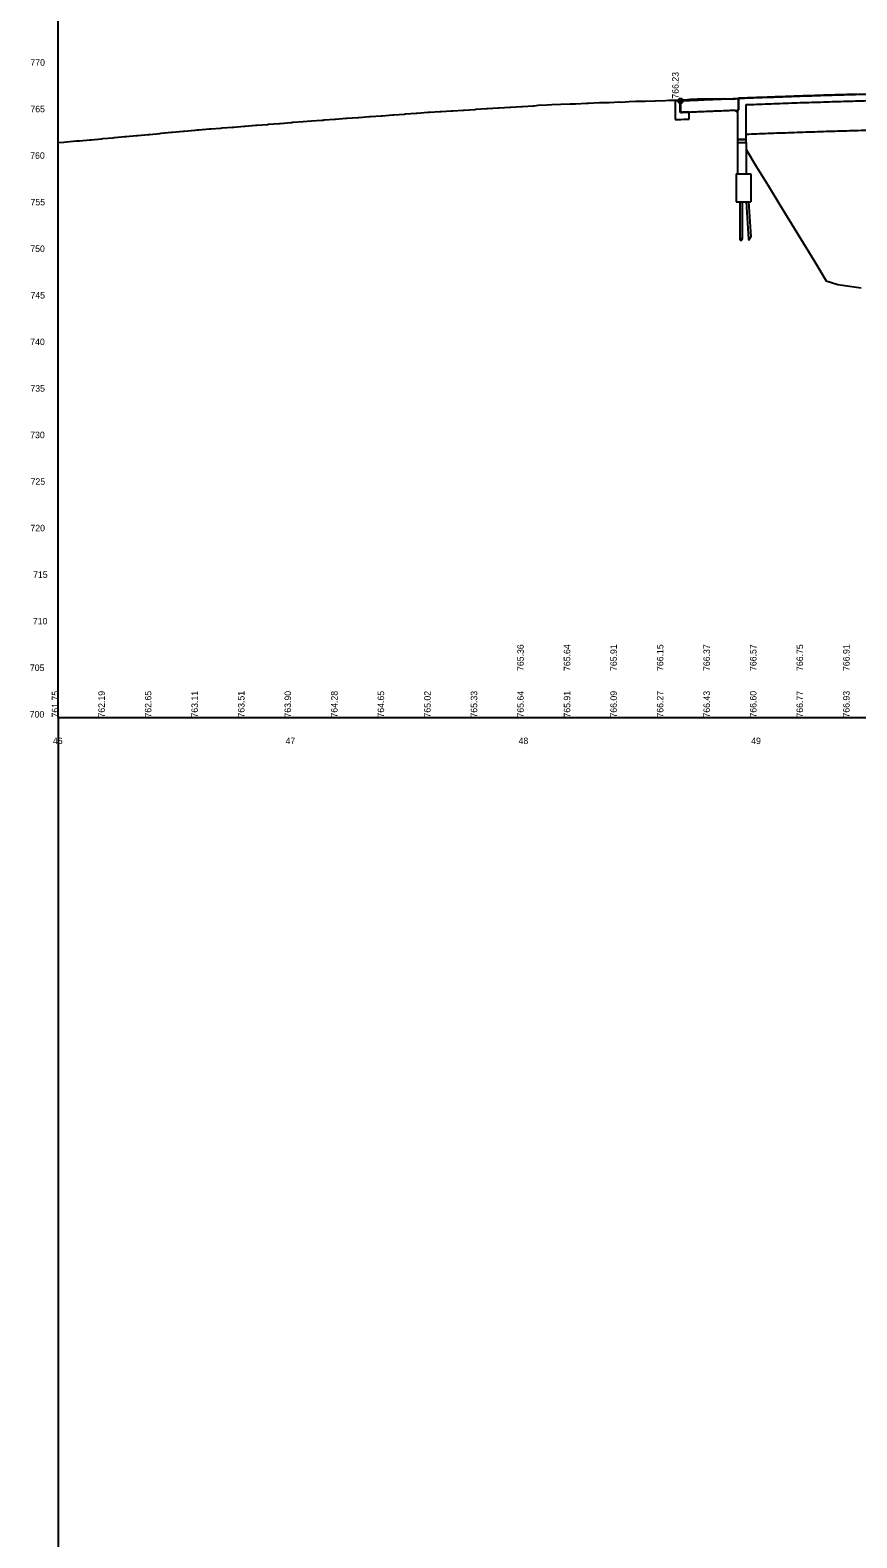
# Model space of a CAD drawing. Extents: x -209 to 3291, y 1080 to 3580.
# Drawn here: x -21 to 334, y 1728 to 2375 of the extents above; entities that cross this region are included whole.
import ezdxf

# ---------------------------------------------------------------- set-up
doc = ezdxf.new("R2010")
doc.units = 0
for name, color, linetype in [('BR_P_Gen_Approach_Slab', 7, 'Continuous'), ('BR_P_Gen_Approach_Slab_Hidden', 7, 'Continuous'), ('BR_P_Gen_Joint_Filler', 7, 'Continuous'), ('BR_P_Slab_Object', 7, 'Continuous'), ('BR_X_Sub_Foot_Object', 7, 'Continuous'), ('Default', 7, 'Continuous'), ('GK_Cells', 7, 'Continuous'), ('PF_P_Grade_Line', 7, 'Continuous'), ('PF_P_Sta_Elev_Text', 7, 'Continuous'), ('PF_P_Text', 7, 'Continuous'), ('PF_X_Ground_Line', 7, 'Continuous'), ('PF_X_Text', 7, 'Continuous')]:
    doc.layers.add(name, color=color, linetype=linetype)

msp = doc.modelspace()

# ---------------------------------------------------------------- linework, layer by layer
at = {"layer": 'BR_P_Gen_Approach_Slab'}
for p, q in [((256.35, 2345.06), (256.35, 2336.96)), ((258.57, 2345.06), (256.35, 2345.06)), ((258.35, 2345.06), (258.35, 2340.06)), ((262.36, 2337.23), (262.36, 2340.23))]:
    msp.add_line(p, q, dxfattribs=at)
msp.add_spline([(256.35, 2336.96), (261.27, 2337.18), (262.36, 2337.23)], degree=3, dxfattribs=at)
at = {"layer": 'BR_P_Gen_Approach_Slab_Hidden'}
for p, q in [((258.57, 2340.06), (258.57, 2345.06)), ((282.57, 2340.41), (282.24, 2341.06)), ((282.57, 2340.41), (283.07, 2340.43)), ((283.07, 2328.43), (286.83, 2328.43))]:
    msp.add_line(p, q, dxfattribs=at)
msp.add_spline([(258.57, 2340.06), (261.26, 2340.18), (271.26, 2340.61), (281.26, 2341.02), (282.24, 2341.06)], degree=3, dxfattribs=at)
at = {"layer": 'BR_P_Gen_Joint_Filler'}
for p, q in [((286.83, 2328.43), (283.07, 2328.43)), ((283.07, 2328.43), (283.07, 2327.1)), ((283.07, 2327.1), (286.83, 2327.1)), ((286.83, 2327.1), (286.83, 2328.43))]:
    msp.add_line(p, q, dxfattribs=at)
at = {"layer": 'BR_P_Slab_Object'}
for p, q in [((283.57, 2346.12), (283.57, 2341.12)), ((283.07, 2341.1), (283.57, 2341.12)), ((283.07, 2341.1), (283.07, 2327.1)), ((286.83, 2327.1), (286.83, 2343.41))]:
    msp.add_line(p, q, dxfattribs=at)
at = {"layer": 'BR_X_Sub_Foot_Object'}
for p, q in [((283.07, 2327.1), (283.07, 2313.73)), ((283.07, 2327.1), (286.83, 2327.1)), ((286.83, 2327.1), (286.83, 2313.73)), ((282.57, 2313.73), (282.57, 2301.73)), ((282.57, 2313.73), (288.84, 2313.73)), ((288.84, 2313.73), (288.84, 2301.73)), ((282.57, 2301.73), (288.84, 2301.73)), ((282.57, 2301.73), (284.57, 2301.73)), ((284.07, 2301.73), (284.07, 2285.6)), ((284.07, 2301.73), (285.07, 2301.73)), ((285.07, 2301.73), (285.07, 2285.6)), ((286.82, 2301.73), (287.83, 2285.6)), ((286.84, 2301.73), (287.84, 2301.73)), ((287.85, 2301.73), (288.8, 2286.57))]:
    msp.add_line(p, q, dxfattribs=at)
for centre, major_axis, start_param, end_param in [((288.12, 2285.01), (0, 1.32), 5.66656, 7.389768), ((288.5, 2287.16), (0, -1.32), 5.66656, 7.389768), ((284.32, 2284.75), (0, 1.32), 5.421581, 7.144789), ((284.32, 2286.46), (0, 1.32), 2.279989, 4.003197), ((284.82, 2286.46), (0, -1.32), 5.421581, 7.144789), ((288.02, 2286.68), (0, 1.32), 2.524967, 4.248175)]:
    msp.add_ellipse(centre, major_axis=major_axis, ratio=0.25, start_param=start_param, end_param=end_param, dxfattribs=at)
msp.add_spline([(286.83, 2330.74), (291.26, 2330.91), (301.26, 2331.28), (311.26, 2331.63), (321.26, 2331.96), (331.26, 2332.26), (341.26, 2332.55), (351.26, 2332.81), (361.26, 2333.06), (371.26, 2333.28), (381.26, 2333.48), (391.26, 2333.66), (401.26, 2333.82), (411.26, 2333.96), (421.26, 2334.07), (431.26, 2334.17), (441.26, 2334.24), (451.26, 2334.3), (461.26, 2334.33), (471.26, 2334.34), (481.26, 2334.33), (491.26, 2334.3), (501.26, 2334.25), (511.26, 2334.18), (521.26, 2334.09), (531.26, 2333.97), (541.26, 2333.84), (551.26, 2333.68), (561.26, 2333.51), (571.26, 2333.31), (581.26, 2333.09), (591.26, 2332.85), (596.07, 2332.73)], degree=3, dxfattribs=at)
at = {"layer": 'Default'}
for p, q in [((257.57, 2345.06), (256.35, 2345.06)), ((256.35, 2345.06), (256.35, 2336.96)), ((283.57, 2341.12), (283.57, 2345.98)), ((258.57, 2344.06), (258.57, 2340.06)), ((258.57, 2340.06), (258.57, 2344.06)), ((262.36, 2337.23), (262.36, 2340.23)), ((282.24, 2341.06), (282.57, 2340.41)), ((282.57, 2340.41), (283.07, 2340.43)), ((283.57, 2341.12), (283.07, 2341.1)), ((283.07, 2341.1), (283.28, 2341.11)), ((283.07, 2340.43), (283.07, 2341.1)), ((283.28, 2341.11), (283.57, 2341.12)), ((283.07, 2328.43), (286.83, 2328.43))]:
    msp.add_line(p, q, dxfattribs=at)
for points in [[(283.57, 2345.98), (280.55, 2345.81), (277.11, 2345.86)], [(283.57, 2346.12), (283.57, 2345.98), (283.57, 2341.12)], [(300.38, 2346.75), (300.37, 2346.75), (300.35, 2346.75)], [(283.07, 2341.1), (283.07, 2340.43), (283.07, 2328.43)], [(286.83, 2328.43), (286.83, 2330.74), (286.83, 2343.41)]]:
    msp.add_lwpolyline(points, dxfattribs=at)
for start, end in [(180, 270), (270, 2.55698)]:
    msp.add_arc((258.57, 2345.06), 1, start, end, dxfattribs=at)
for points in [[(277.11, 2345.86), (271.26, 2345.61), (261.26, 2345.18), (259.57, 2345.11)], [(300.35, 2346.75), (291.26, 2346.41), (283.57, 2346.12)], [(286.83, 2343.41), (291.26, 2343.58), (301.26, 2343.95), (311.26, 2344.3), (321.26, 2344.62), (331.26, 2344.93), (341.26, 2345.22), (351.26, 2345.48), (361.26, 2345.72), (371.26, 2345.94), (381.26, 2346.14), (391.26, 2346.32), (401.26, 2346.48), (411.26, 2346.62), (421.26, 2346.74), (431.26, 2346.83), (441.26, 2346.91), (451.26, 2346.96), (461.26, 2347), (471.26, 2347.01), (481.26, 2347), (491.26, 2346.97), (501.26, 2346.92), (511.26, 2346.85), (521.26, 2346.75), (531.26, 2346.64), (541.26, 2346.51), (551.26, 2346.35), (561.26, 2346.17), (571.26, 2345.97), (581.26, 2345.76), (591.26, 2345.52), (596.07, 2345.39)], [(334.38, 2347.85), (331.26, 2347.76), (321.26, 2347.46), (311.26, 2347.13), (301.26, 2346.78), (300.38, 2346.75)], [(256.35, 2336.96), (261.27, 2337.18), (262.36, 2337.23)]]:
    msp.add_spline(points, degree=3, dxfattribs=at)
for points in [[(258.57, 2340.06), (259.47, 2340.1), (260.36, 2340.14), (261.26, 2340.18), (264.59, 2340.33), (267.92, 2340.47), (271.26, 2340.61), (274.59, 2340.75), (277.92, 2340.89), (281.26, 2341.02), (281.59, 2341.04), (281.91, 2341.05), (282.24, 2341.06)], [(262.36, 2340.23), (261.99, 2340.21), (261.63, 2340.2), (261.26, 2340.18), (260.36, 2340.14), (259.47, 2340.1), (258.57, 2340.06)]]:
    msp.add_open_spline(points, degree=3, dxfattribs=at)
at = {"layer": 'GK_Cells'}
for q in [(-8.74, 3080.13), (3291.26, 2080.13), (-8.74, 1080.13)]:
    msp.add_line((-8.74, 2080.13), q, dxfattribs=at)
at = {"layer": 'PF_P_Grade_Line'}
for points in [[(258.57, 2345.06), (261.26, 2345.18), (271.26, 2345.61), (281.26, 2346.02), (291.26, 2346.41), (301.26, 2346.78), (311.26, 2347.13), (321.26, 2347.46), (331.26, 2347.76), (341.26, 2348.05), (351.26, 2348.31), (361.26, 2348.56), (371.26, 2348.78), (381.26, 2348.98), (391.26, 2349.16), (401.26, 2349.32), (411.26, 2349.46), (421.26, 2349.57), (431.26, 2349.67), (441.26, 2349.74), (451.26, 2349.8), (461.26, 2349.83), (471.26, 2349.84), (481.26, 2349.83), (491.26, 2349.8), (501.26, 2349.75), (511.26, 2349.68), (521.26, 2349.59), (531.26, 2349.47), (541.26, 2349.34), (551.26, 2349.18), (561.26, 2349.01), (571.26, 2348.81), (581.26, 2348.59), (591.26, 2348.35), (601.26, 2348.09), (611.26, 2347.81), (621.26, 2347.5), (624.33, 2347.41)], [(286.83, 2343.41), (291.26, 2343.58), (301.26, 2343.95), (311.26, 2344.3), (321.26, 2344.62), (331.26, 2344.93), (341.26, 2345.22), (351.26, 2345.48), (361.26, 2345.72), (371.26, 2345.94), (381.26, 2346.14), (391.26, 2346.32), (401.26, 2346.48), (411.26, 2346.62), (421.26, 2346.74), (431.26, 2346.83), (441.26, 2346.91), (451.26, 2346.96), (461.26, 2347), (471.26, 2347.01), (481.26, 2347), (491.26, 2346.97), (501.26, 2346.92), (511.26, 2346.85), (521.26, 2346.75), (531.26, 2346.64), (541.26, 2346.51), (551.26, 2346.35), (561.26, 2346.17), (571.26, 2345.97), (581.26, 2345.76), (591.26, 2345.52), (596.07, 2345.39)]]:
    msp.add_spline(points, degree=3, dxfattribs=at)
at = {"layer": 'PF_P_Text'}
msp.add_circle((258.57, 2345.06), 1, dxfattribs=at)
at = {"layer": 'PF_X_Ground_Line'}
for points in [[(-8.74, 2327.12), (-6.39, 2327.33), (-5.18, 2327.44), (-0.9, 2327.83), (-0.13, 2327.84), (0.43, 2327.89), (4.87, 2328.3), (5.43, 2328.35), (9.87, 2328.76), (10.42, 2328.81), (14.87, 2329.22), (15.41, 2329.27), (19.87, 2329.68), (20.41, 2329.73), (24.86, 2330.14), (25.4, 2330.19), (29.86, 2330.6), (30.39, 2330.65), (34.86, 2331.06), (35.39, 2331.11), (39.86, 2331.52), (40.38, 2331.57), (44.86, 2331.98), (45.38, 2332.03), (49.86, 2332.44), (50.01, 2332.46), (51.13, 2332.56), (51.64, 2332.61), (56.13, 2332.96), (56.63, 2333), (61.13, 2333.35), (61.62, 2333.39), (66.13, 2333.75), (66.61, 2333.79), (71.13, 2334.14), (71.6, 2334.18), (76.13, 2334.54), (76.59, 2334.58), (81.13, 2334.93), (81.58, 2334.97), (86.13, 2335.33), (86.57, 2335.36), (91.13, 2335.72), (91.56, 2335.76), (92.01, 2335.83), (96.48, 2336.18), (100.03, 2336.45), (104.53, 2336.79), (105, 2336.79), (105.42, 2336.82), (110, 2337.16), (110.42, 2337.19), (114.99, 2337.53), (115.43, 2337.56), (119.99, 2337.9), (120.43, 2337.93), (124.99, 2338.27), (125.44, 2338.3), (129.99, 2338.64), (130.44, 2338.67), (134.98, 2339.01), (135.45, 2339.04), (139.98, 2339.38), (140.45, 2339.41), (144.98, 2339.75), (145.46, 2339.78), (149.97, 2340.12), (150.15, 2340.14), (150.71, 2340.18), (155.23, 2340.46), (155.71, 2340.48), (160.23, 2340.77), (160.71, 2340.79), (165.24, 2341.08), (165.71, 2341.1), (170.25, 2341.39), (170.7, 2341.41), (175.26, 2341.69), (175.7, 2341.72), (180.26, 2342), (180.7, 2342.03), (185.27, 2342.31), (185.7, 2342.34), (190.28, 2342.62), (190.7, 2342.64), (195.29, 2342.93), (195.7, 2342.95), (197.46, 2343.13), (201.34, 2343.37), (203.3, 2343.5), (207.22, 2343.64), (211.17, 2343.78), (213.17, 2343.79), (213.55, 2343.81), (218.17, 2343.98), (219.06, 2344.07), (223.77, 2344.34), (224.57, 2344.37), (225.4, 2344.4), (227.98, 2344.39), (232.46, 2344.55)], [(232.46, 2344.55), (233.17, 2344.54), (236.6, 2344.74), (239.2, 2344.84), (241.84, 2344.93), (243.39, 2344.92), (247.76, 2345.08), (252.15, 2345.24), (253.43, 2345.32), (257.85, 2345.38), (259.15, 2345.42), (259.29, 2345.43), (260.35, 2345.51), (262.71, 2345.74), (263.66, 2345.78), (265.83, 2345.84), (276.61, 2345.86), (280.55, 2345.81), (283.9, 2346), (284.03, 2345.68)], [(285.37, 2346.4), (285.37, 2346.4), (285.37, 2346.4), (290.37, 2346.51), (295.37, 2346.64), (300.37, 2346.75), (305.37, 2347.01), (310.37, 2347.18), (315.37, 2347.37), (320.37, 2347.53), (325.37, 2347.69), (330.37, 2347.83), (335.37, 2347.86)], [(286.83, 2324.07), (291.26, 2316.74), (296.26, 2308.62), (301.26, 2300.43), (306.26, 2292.24), (311.26, 2284.06), (316.26, 2275.88), (321.26, 2267.71), (326.26, 2266.18), (331.26, 2265.46), (336.26, 2264.75)]]:
    msp.add_lwpolyline(points, dxfattribs=at)

# ---------------------------------------------------------------- texts
at = {"layer": 'GK_Cells'}
for s, p in [('450', (-8.74, 2081.6)), ('WINCHESTER', (-8.74, 2081.39)), ('4600.000000', (-8.74, 2081.18)), ('700', (-8.74, 2080.97)), ('20', (-8.74, 2080.76)), ('5', (-8.74, 2080.55)), ('NOGAP', (-8.74, 2080.34))]:
    msp.add_text(s, height=0.14, dxfattribs=at).set_placement(p)
at = {"layer": 'PF_P_Sta_Elev_Text'}
for s, p in [('770', (-20.73, 2360.13)), ('770', (-20.73, 2360.13)), ('765', (-20.73, 2340.13)), ('765', (-20.73, 2340.13)), ('760', (-20.82, 2320.13)), ('760', (-20.82, 2320.13)), ('755', (-20.69, 2300.13)), ('755', (-20.69, 2300.13)), ('750', (-20.77, 2280.13)), ('750', (-20.77, 2280.13)), ('745', (-20.71, 2260.13)), ('745', (-20.71, 2260.13)), ('740', (-20.8, 2240.13)), ('740', (-20.8, 2240.13)), ('735', (-20.73, 2220.13)), ('735', (-20.73, 2220.13)), ('730', (-20.82, 2200.13)), ('730', (-20.82, 2200.13)), ('725', (-20.64, 2180.13)), ('725', (-20.64, 2180.13)), ('720', (-20.73, 2160.13)), ('720', (-20.73, 2160.13)), ('715', (-19.58, 2140.13)), ('715', (-19.58, 2140.13)), ('710', (-19.67, 2120.13)), ('710', (-19.67, 2120.13)), ('705', (-20.95, 2100.13)), ('705', (-20.95, 2100.13)), ('700', (-21.04, 2080.13)), ('700', (-21.04, 2080.13)), ('46', (-11.05, 2068.73)), ('47', (88.9, 2068.73)), ('48', (189.02, 2068.73)), ('49', (288.98, 2068.73))]:
    msp.add_text(s, height=2.8, dxfattribs=at).set_placement(p)
at = {"layer": 'PF_P_Text'}
for s, p in [('766.23', (257.81, 2345.99)), ('765.36', (191.26, 2100.13)), ('765.64', (211.26, 2100.13)), ('765.91', (231.26, 2100.13)), ('766.15', (251.26, 2100.13)), ('766.37', (271.26, 2100.13)), ('766.57', (291.26, 2100.13)), ('766.57', (291.26, 2100.13)), ('766.75', (311.26, 2100.13)), ('766.75', (311.26, 2100.13)), ('766.91', (331.26, 2100.13)), ('766.91', (331.26, 2100.13))]:
    msp.add_text(s, height=2.8, rotation=90, dxfattribs=at).set_placement(p)
at = {"layer": 'PF_X_Text'}
for s, p in [('761.75', (-8.74, 2080.13)), ('762.19', (11.26, 2080.13)), ('762.65', (31.26, 2080.13)), ('763.11', (51.26, 2080.13)), ('763.51', (71.26, 2080.13)), ('763.90', (91.26, 2080.13)), ('764.28', (111.26, 2080.13)), ('764.65', (131.26, 2080.13)), ('765.02', (151.26, 2080.13)), ('765.33', (171.26, 2080.13)), ('765.64', (191.26, 2080.13)), ('765.91', (211.26, 2080.13)), ('766.09', (231.26, 2080.13)), ('766.27', (251.26, 2080.13)), ('766.43', (271.26, 2080.13)), ('766.60', (291.26, 2080.13)), ('766.77', (311.26, 2080.13)), ('766.93', (331.26, 2080.13))]:
    msp.add_text(s, height=2.8, rotation=90, dxfattribs=at).set_placement(p)

doc.saveas('drawing.dxf')
